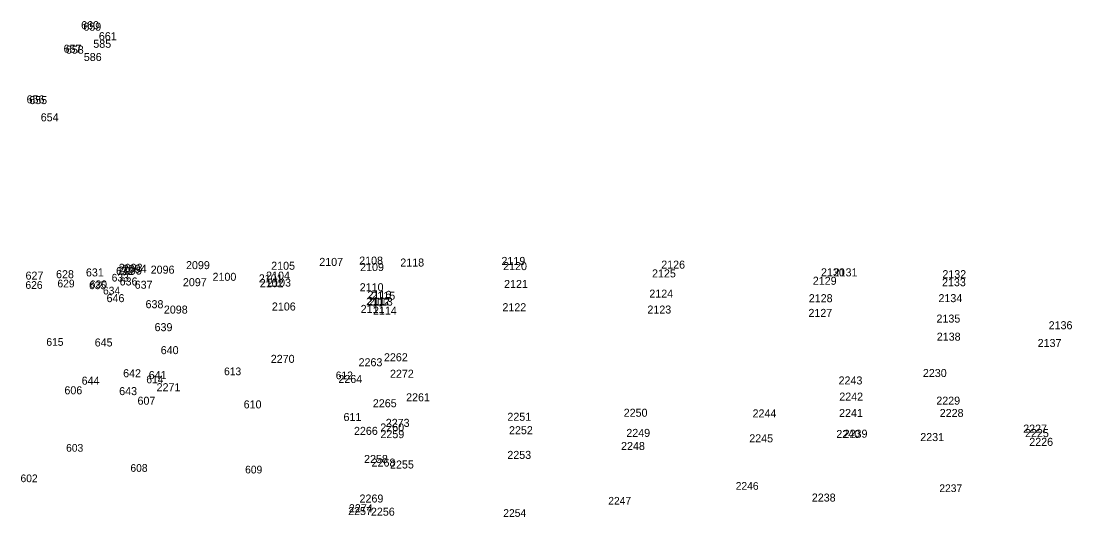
# Model space of a CAD drawing. Extents: x 359002 to 361405, y 1522603 to 1525369.
# Drawn here: x 360195.9 to 360524.3, y 1524618.5 to 1524773.4 of the extents above; entities that cross this region are included whole.
import ezdxf

# ---------------------------------------------------------------- set-up
doc = ezdxf.new("R2010")
doc.units = 0
for name, color, linetype in [('BSUBM_I', 7, 'Continuous'), ('BVC_I', 7, 'Continuous'), ('DINV_I', 7, 'Continuous'), ('LABL_I', 7, 'Continuous'), ('LARR_I', 7, 'Continuous'), ('LELB_I', 7, 'Continuous'), ('LELS_I', 7, 'Continuous'), ('LFNC_I', 7, 'Continuous'), ('LS_I', 7, 'Continuous'), ('PE_I', 7, 'Continuous'), ('RC_I', 7, 'Continuous'), ('RDP_I', 7, 'Continuous'), ('RGB_I', 7, 'Continuous'), ('RGW_I', 7, 'Continuous'), ('SDEL_I', 7, 'Continuous'), ('SRM_I', 7, 'Continuous'), ('UEO_I', 7, 'Continuous'), ('ULP_I', 7, 'Continuous'), ('UP_I', 7, 'Continuous'), ('UPGW_I', 7, 'Continuous')]:
    doc.layers.add(name, color=color, linetype=linetype)

msp = doc.modelspace()

# ---------------------------------------------------------------- texts
at = {"layer": 'BSUBM_I'}
for s, p in [('661', (360220.21, 1524767.43)), ('654', (360202.05, 1524742.09))]:
    msp.add_text(s, height=2.501, dxfattribs=at).set_placement(p)
at = {"layer": 'BVC_I'}
for s, p in [('585', (360218.48, 1524765.06)), ('586', (360215.51, 1524760.93))]:
    msp.add_text(s, height=2.501, dxfattribs=at).set_placement(p)
at = {"layer": 'DINV_I'}
msp.add_text('2117', height=2.501, dxfattribs=at).set_placement((360304, 1524684.73))
at = {"layer": 'LABL_I'}
for s, p in [('2098', (360240.53, 1524682.03)), ('2098', (360240.53, 1524682.03)), ('2106', (360274.29, 1524682.99)), ('2122', (360346.33, 1524682.77)), ('2123', (360391.64, 1524682.04)), ('2127', (360441.96, 1524680.99)), ('2135', (360481.98, 1524679.22)), ('2136', (360517.03, 1524677.14)), ('2138', (360482.07, 1524673.57)), ('2137', (360513.59, 1524671.59)), ('2270', (360273.94, 1524666.64)), ('2264', (360295.06, 1524660.35)), ('2230', (360477.73, 1524662.22)), ('2271', (360238.26, 1524657.78)), ('2271', (360238.26, 1524657.78)), ('2242', (360451.6, 1524654.85)), ('2252', (360348.39, 1524644.35))]:
    msp.add_text(s, height=2.501, dxfattribs=at).set_placement(p)
at = {"layer": 'LARR_I'}
for s, p in [('636', (360226.71, 1524690.82)), ('636', (360226.71, 1524690.82)), ('637', (360231.41, 1524689.79)), ('646', (360222.62, 1524685.6)), ('646', (360222.62, 1524685.6)), ('638', (360234.81, 1524683.71)), ('2111', (360302.03, 1524682.24)), ('2114', (360305.88, 1524681.69)), ('639', (360237.63, 1524676.54)), ('645', (360218.92, 1524671.76)), ('640', (360239.55, 1524669.36)), ('2262', (360309.31, 1524667.14)), ('2263', (360301.38, 1524665.58)), ('642', (360227.8, 1524662.15)), ('641', (360235.78, 1524661.57)), ('644', (360214.83, 1524659.82)), ('643', (360226.56, 1524656.56)), ('2265', (360305.84, 1524652.77)), ('2244', (360424.5, 1524649.6)), ('2228', (360482.99, 1524649.74)), ('2266', (360299.94, 1524644.14)), ('2266', (360299.94, 1524644.14)), ('2260', (360308.17, 1524645.2)), ('2252', (360348.39, 1524644.35)), ('2227', (360509.08, 1524644.85)), ('2226', (360510.98, 1524640.72)), ('2258', (360303.09, 1524635.37)), ('2257', (360298.11, 1524619.1))]:
    msp.add_text(s, height=2.501, dxfattribs=at).set_placement(p)
at = {"layer": 'LELB_I'}
for s, p in [('628', (360206.83, 1524693.08)), ('631', (360216.17, 1524693.64)), ('632', (360225.57, 1524694.11)), ('2095', (360226.2, 1524694.23)), ('2096', (360236.41, 1524694.5)), ('2105', (360274.07, 1524695.72)), ('2109', (360301.86, 1524695.32)), ('2120', (360346.56, 1524695.61)), ('2125', (360393.09, 1524693.33)), ('627', (360197.3, 1524692.64)), ('2097', (360246.48, 1524690.59)), ('2102', (360270.51, 1524690.28)), ('2103', (360272.81, 1524690.46)), ('2121', (360346.85, 1524690.03)), ('2129', (360443.33, 1524691.03)), ('2133', (360483.71, 1524690.58)), ('2110', (360301.74, 1524689.01)), ('2116', (360304.16, 1524686.64)), ('2124', (360392.24, 1524687.01)), ('2112', (360303.75, 1524684.59)), ('2113', (360304.61, 1524684.52)), ('2115', (360305.39, 1524686.37)), ('2128', (360442.07, 1524685.59)), ('2134', (360482.59, 1524685.6)), ('2111', (360302.03, 1524682.24)), ('2114', (360305.88, 1524681.69)), ('2230', (360477.73, 1524662.22)), ('2243', (360451.38, 1524659.9)), ('606', (360209.45, 1524656.82)), ('2261', (360316.23, 1524654.63)), ('607', (360232.29, 1524653.56)), ('610', (360265.47, 1524652.41)), ('2265', (360305.84, 1524652.77)), ('2265', (360305.84, 1524652.77)), ('611', (360296.67, 1524648.47)), ('2251', (360347.88, 1524648.55)), ('2250', (360384.23, 1524649.81)), ('2244', (360424.5, 1524649.6)), ('2241', (360451.54, 1524649.73)), ('2228', (360482.99, 1524649.74)), ('2252', (360348.39, 1524644.35)), ('2259', (360308.21, 1524643.12)), ('2249', (360385.05, 1524643.51)), ('2225', (360509.65, 1524643.44)), ('2268', (360305.45, 1524634.24)), ('2269', (360301.68, 1524623.01))]:
    msp.add_text(s, height=2.501, dxfattribs=at).set_placement(p)
at = {"layer": 'LELS_I'}
for s, p in [('629', (360207.28, 1524690.22)), ('630', (360217.4, 1524690)), ('633', (360224.21, 1524692.05)), ('626', (360197.27, 1524689.76)), ('635', (360217.14, 1524689.66)), ('634', (360221.5, 1524688.01)), ('615', (360203.81, 1524671.97)), ('613', (360259.34, 1524662.79)), ('612', (360294.25, 1524661.53)), ('614', (360235.04, 1524660.27)), ('603', (360209.98, 1524638.88)), ('608', (360230.08, 1524632.61)), ('609', (360265.92, 1524632.1)), ('602', (360195.73, 1524629.37)), ('2246', (360419.24, 1524626.99)), ('2237', (360482.87, 1524626.28)), ('2247', (360379.41, 1524622.36)), ('2254', (360346.6, 1524618.53))]:
    msp.add_text(s, height=2.4, dxfattribs=at).set_placement(p)
at = {"layer": 'LFNC_I'}
for s, p in [('2240', (360450.67, 1524643.18)), ('2238', (360443.02, 1524623.31))]:
    msp.add_text(s, height=2.501, dxfattribs=at).set_placement(p)
at = {"layer": 'LS_I'}
for s, p in [('2101', (360270.2, 1524691.78)), ('2102', (360270.51, 1524690.28)), ('2104', (360272.48, 1524692.65)), ('2103', (360272.81, 1524690.46))]:
    msp.add_text(s, height=2.501, dxfattribs=at).set_placement(p)
at = {"layer": 'PE_I'}
for s, p in [('660', (360214.67, 1524770.88)), ('657', (360209.19, 1524763.52)), ('656', (360197.63, 1524747.71))]:
    msp.add_text(s, height=2.501, dxfattribs=at).set_placement(p)
at = {"layer": 'RC_I'}
for s, p in [('659', (360215.37, 1524770.39)), ('658', (360209.89, 1524763.22)), ('655', (360198.45, 1524747.47))]:
    msp.add_text(s, height=2.501, dxfattribs=at).set_placement(p)
at = {"layer": 'RDP_I'}
for s, p in [('2245', (360423.47, 1524641.82)), ('2239', (360452.97, 1524643.26)), ('2231', (360476.91, 1524642.21)), ('2226', (360510.98, 1524640.72)), ('2248', (360383.41, 1524639.42)), ('2253', (360347.87, 1524636.64)), ('2255', (360311.21, 1524633.64)), ('2256', (360305.24, 1524618.9))]:
    msp.add_text(s, height=2.501, dxfattribs=at).set_placement(p)
at = {"layer": 'RGB_I'}
for s, p in [('2107', (360289.1, 1524696.93)), ('2108', (360301.57, 1524697.33)), ('2093', (360226.43, 1524695.09)), ('2099', (360247.45, 1524695.91)), ('2099', (360247.45, 1524695.91)), ('2100', (360255.74, 1524692.27))]:
    msp.add_text(s, height=2.501, dxfattribs=at).set_placement(p)
at = {"layer": 'RGW_I'}
for s, p in [('2108', (360301.57, 1524697.33)), ('2119', (360346.04, 1524697.23)), ('2126', (360395.96, 1524696.07)), ('2130', (360445.88, 1524693.68)), ('2132', (360483.82, 1524693.09))]:
    msp.add_text(s, height=2.501, dxfattribs=at).set_placement(p)
at = {"layer": 'SDEL_I'}
for s, p in [('2118', (360314.42, 1524696.73)), ('2131', (360449.84, 1524693.65))]:
    msp.add_text(s, height=2.501, dxfattribs=at).set_placement(p)
at = {"layer": 'SRM_I'}
msp.add_text('2094', height=2.501, dxfattribs=at).set_placement((360227.68, 1524694.77))
at = {"layer": 'UEO_I'}
for s, p in [('2273', (360309.87, 1524646.65)), ('2274', (360298.35, 1524619.98))]:
    msp.add_text(s, height=2.501, dxfattribs=at).set_placement(p)
at = {"layer": 'ULP_I'}
msp.add_text('2229', height=2.501, dxfattribs=at).set_placement((360481.92, 1524653.58))
at = {"layer": 'UP_I'}
msp.add_text('2273', height=2.501, dxfattribs=at).set_placement((360309.87, 1524646.65))
at = {"layer": 'UPGW_I'}
msp.add_text('2272', height=2.501, dxfattribs=at).set_placement((360311.2, 1524662))

doc.saveas('drawing.dxf')
